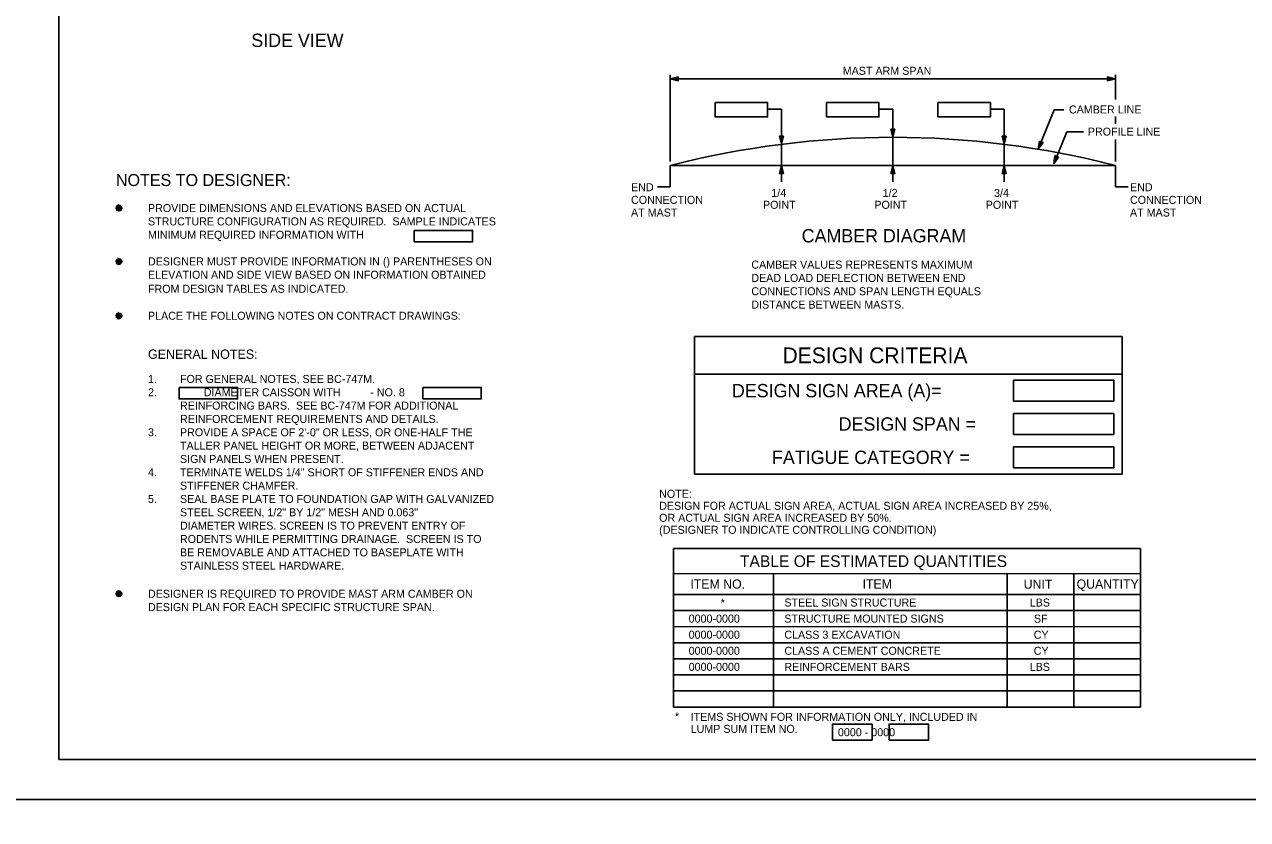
# Model space of a CAD drawing. Extents: x 640117 to 642655, y 297247 to 298435.
# Drawn here: x 640985.6 to 641443.9, y 297834 to 298132 of the extents above; entities that cross this region are included whole.
import ezdxf

# ---------------------------------------------------------------- set-up
doc = ezdxf.new("R2010")
doc.units = 0
for name, color, linetype in [('10', 7, 'Continuous'), ('17', 7, 'Continuous'), ('2', 7, 'Continuous'), ('52', 7, 'Continuous'), ('53', 7, 'Continuous'), ('55', 7, 'Continuous'), ('PLT-BNDY', 7, 'Continuous')]:
    doc.layers.add(name, color=color, linetype=linetype)

msp = doc.modelspace()

# ---------------------------------------------------------------- linework, layer by layer
at = {"layer": '10'}
for points in [[(641244.43, 298102.74), (641244.43, 298097.37), (641264.07, 298097.37), (641264.07, 298102.74)], [(641286.17, 298102.74), (641286.17, 298097.37), (641305.82, 298097.37), (641305.82, 298102.74)], [(641327.92, 298102.74), (641327.92, 298097.37), (641347.56, 298097.37), (641347.56, 298102.74)], [(641356.29, 297990.83), (641393.79, 297990.83), (641393.79, 297998.64), (641356.29, 297998.65)], [(641356.29, 297978.33), (641393.79, 297978.33), (641393.79, 297986.14), (641356.29, 297986.15)], [(641356.29, 297965.83), (641393.79, 297965.83), (641393.79, 297973.64), (641356.29, 297973.65)], [(641288.41, 297863.76), (641303.23, 297863.76), (641303.23, 297869.73), (641288.41, 297869.73)], [(641309.61, 297863.76), (641324.42, 297863.76), (641324.42, 297869.73), (641309.61, 297869.73)]]:
    msp.add_lwpolyline(points, close=True, dxfattribs=at)
at = {"layer": '17'}
for p, q in [((641396.92, 298014.99), (641236.73, 298014.99)), ((641236.73, 298014.99), (641236.73, 297963.49)), ((641396.92, 298014.99), (641396.92, 297963.49)), ((641236.73, 298000.99), (641396.92, 298000.99)), ((641236.73, 297963.49), (641396.92, 297963.49)), ((641228.81, 297935.51), (641228.81, 297876.12)), ((641403.81, 297935.51), (641228.81, 297935.51)), ((641403.81, 297935.51), (641403.81, 297876.12)), ((641403.81, 297926.13), (641228.81, 297926.14)), ((641266.31, 297926.14), (641266.31, 297876.12)), ((641353.81, 297926.13), (641353.81, 297876.13)), ((641378.81, 297926.13), (641378.81, 297876.13)), ((641403.81, 297918.32), (641228.81, 297918.32)), ((641403.81, 297912.29), (641228.81, 297912.3)), ((641403.81, 297906.26), (641228.81, 297906.27)), ((641403.81, 297900.23), (641228.81, 297900.24)), ((641403.81, 297894.21), (641228.81, 297894.21)), ((641403.81, 297888.18), (641228.81, 297888.18)), ((641403.81, 297882.15), (641228.81, 297882.15)), ((641403.81, 297876.12), (641228.81, 297876.12))]:
    msp.add_line(p, q, dxfattribs=at)
at = {"layer": '2'}
for p, q in [((640998.46, 297856.46), (640998.46, 298420.46)), ((641784.46, 297856.46), (640998.46, 297856.46))]:
    msp.add_line(p, q, dxfattribs=at)
for points in [[(641131.65, 298054.82), (641153.54, 298054.82), (641153.54, 298050.51), (641131.65, 298050.51)], [(641043.55, 297995.95), (641065.44, 297995.95), (641065.44, 297991.64), (641043.55, 297991.64)], [(641134.9, 297995.95), (641156.79, 297995.95), (641156.79, 297991.64), (641134.9, 297991.64)]]:
    msp.add_lwpolyline(points, close=True, dxfattribs=at)
for centre, radius in [((641020.98, 298063.2), 1.04), ((641020.98, 298063.2), 0.781), ((641020.98, 298063.2), 0.521), ((641020.98, 298063.2), 0.26), ((641020.98, 298063.2), 0.00000208), ((641020.98, 298043.12), 1.04), ((641020.98, 298043.12), 0.781), ((641020.98, 298043.12), 0.521), ((641020.98, 298043.12), 0.26), ((641020.98, 298043.12), 0.00000208), ((641020.98, 298022.75), 1.04), ((641020.98, 298022.75), 0.781), ((641020.98, 298022.75), 0.521), ((641020.98, 298022.75), 0.26), ((641020.98, 298022.75), 0.00000208), ((641020.98, 297918.62), 1.04), ((641020.98, 297918.62), 0.781), ((641020.98, 297918.62), 0.521), ((641020.98, 297918.62), 0.26), ((641020.98, 297918.62), 0.00000208)]:
    msp.add_circle(centre, radius, dxfattribs=at)
at = {"layer": '52'}
for p, q in [((641227.54, 298080.63), (641227.54, 298113.15)), ((641230.54, 298112.4), (641227.54, 298111.65)), ((641227.54, 298111.65), (641394.51, 298111.65)), ((641227.54, 298111.65), (641230.54, 298110.91)), ((641230.37, 298112.18), (641228.28, 298111.65)), ((641228.28, 298111.65), (641230.37, 298111.13)), ((641230.19, 298111.95), (641229.01, 298111.65)), ((641229.01, 298111.65), (641230.19, 298111.36)), ((641230.12, 298111.75), (641229.74, 298111.65)), ((641229.74, 298111.65), (641230.1, 298111.56)), ((641230.19, 298111.36), (641230.19, 298111.95)), ((641230.37, 298111.13), (641230.37, 298112.18)), ((641230.54, 298110.91), (641230.54, 298112.4)), ((641394.51, 298111.65), (641391.51, 298112.4)), ((641391.51, 298112.4), (641391.51, 298110.91)), ((641391.51, 298110.91), (641394.51, 298111.65)), ((641393.77, 298111.65), (641391.68, 298112.18)), ((641391.68, 298112.18), (641391.68, 298111.13)), ((641391.68, 298111.13), (641393.77, 298111.65)), ((641393.04, 298111.65), (641391.86, 298111.95)), ((641391.86, 298111.95), (641391.86, 298111.36)), ((641391.86, 298111.36), (641393.04, 298111.65)), ((641391.93, 298111.56), (641392.31, 298111.65)), ((641392.31, 298111.65), (641391.95, 298111.74)), ((641394.51, 298103.96), (641394.51, 298113.15)), ((641264.07, 298100.3), (641269.28, 298100.3)), ((641305.82, 298100.3), (641311.02, 298100.3)), ((641347.56, 298100.3), (641352.77, 298100.3)), ((641394.51, 298094.75), (641394.51, 298097.55)), ((641310.28, 298092.72), (641311.02, 298089.72)), ((641311.77, 298092.72), (641310.28, 298092.72)), ((641310.5, 298092.54), (641311.02, 298090.45)), ((641311.55, 298092.54), (641310.5, 298092.54)), ((641310.73, 298092.36), (641311.02, 298091.18)), ((641311.32, 298092.36), (641310.73, 298092.36)), ((641310.93, 298092.29), (641311.02, 298091.91)), ((641311.02, 298089.72), (641311.77, 298092.72)), ((641311.02, 298090.45), (641311.55, 298092.54)), ((641311.02, 298091.18), (641311.32, 298092.36)), ((641311.02, 298091.91), (641311.11, 298092.27)), ((641382.52, 298091.78), (641376.19, 298091.78)), ((641268.53, 298090.1), (641269.28, 298087.1)), ((641270.03, 298090.1), (641268.53, 298090.1)), ((641268.76, 298089.92), (641269.28, 298087.83)), ((641269.81, 298089.92), (641268.76, 298089.92)), ((641268.99, 298089.75), (641269.28, 298088.57)), ((641269.58, 298089.75), (641268.99, 298089.75)), ((641269.19, 298089.68), (641269.28, 298089.3)), ((641269.28, 298087.1), (641270.03, 298090.1)), ((641269.28, 298087.83), (641269.81, 298089.92)), ((641269.28, 298088.57), (641269.58, 298089.75)), ((641269.28, 298089.3), (641269.37, 298089.66)), ((641352.02, 298090.1), (641352.77, 298087.1)), ((641353.51, 298090.1), (641352.02, 298090.1)), ((641352.24, 298089.92), (641352.77, 298087.83)), ((641353.29, 298089.92), (641352.24, 298089.92)), ((641352.47, 298089.75), (641352.77, 298088.57)), ((641353.06, 298089.75), (641352.47, 298089.75)), ((641352.67, 298089.68), (641352.77, 298089.3)), ((641352.77, 298087.1), (641353.51, 298090.1)), ((641352.77, 298087.83), (641353.29, 298089.92)), ((641352.77, 298088.57), (641353.06, 298089.75)), ((641352.77, 298089.3), (641352.86, 298089.66)), ((641365.96, 298088.31), (641365.52, 298085.25)), ((641365.52, 298085.25), (641367.35, 298087.74)), ((641366.1, 298088.06), (641365.8, 298085.93)), ((641365.8, 298085.93), (641367.07, 298087.66)), ((641367.35, 298087.74), (641365.96, 298088.31)), ((641366.25, 298087.81), (641366.07, 298086.61)), ((641366.07, 298086.61), (641366.79, 298087.59)), ((641367.07, 298087.66), (641366.1, 298088.06)), ((641366.79, 298087.59), (641366.25, 298087.81)), ((641366.41, 298087.67), (641366.35, 298087.28)), ((641366.35, 298087.28), (641366.57, 298087.58)), ((641394.51, 298080.63), (641394.51, 298088.9)), ((641371.76, 298082.88), (641371.32, 298079.82)), ((641371.32, 298079.82), (641373.15, 298082.32)), ((641371.9, 298082.63), (641371.6, 298080.5)), ((641371.6, 298080.5), (641372.87, 298082.24)), ((641373.15, 298082.32), (641371.76, 298082.88)), ((641372.04, 298082.38), (641371.87, 298081.18)), ((641372.87, 298082.24), (641371.9, 298082.63)), ((641372.59, 298082.16), (641372.04, 298082.38)), ((641372.21, 298082.24), (641372.15, 298081.86)), ((641227.54, 298079.13), (641227.54, 298071.19)), ((641269.28, 298079.13), (641268.53, 298076.13)), ((641269.28, 298078.4), (641268.76, 298076.31)), ((641269.28, 298077.67), (641268.99, 298076.49)), ((641270.03, 298076.13), (641269.28, 298079.13)), ((641269.81, 298076.31), (641269.28, 298078.4)), ((641269.58, 298076.49), (641269.28, 298077.67)), ((641311.02, 298079.13), (641310.28, 298076.13)), ((641311.02, 298078.4), (641310.5, 298076.31)), ((641311.02, 298077.67), (641310.73, 298076.49)), ((641311.77, 298076.13), (641311.02, 298079.13)), ((641311.55, 298076.31), (641311.02, 298078.4)), ((641311.32, 298076.49), (641311.02, 298077.67)), ((641352.77, 298079.13), (641352.02, 298076.13)), ((641352.77, 298078.4), (641352.24, 298076.31)), ((641352.77, 298077.67), (641352.47, 298076.49)), ((641353.51, 298076.13), (641352.77, 298079.13)), ((641353.29, 298076.31), (641352.77, 298078.4)), ((641353.06, 298076.49), (641352.77, 298077.67)), ((641371.87, 298081.18), (641372.59, 298082.16)), ((641372.15, 298081.86), (641372.37, 298082.15)), ((641394.51, 298079.13), (641394.51, 298071.19)), ((641268.53, 298076.13), (641270.03, 298076.13)), ((641268.76, 298076.31), (641269.81, 298076.31)), ((641268.99, 298076.49), (641269.58, 298076.49)), ((641269.28, 298076.93), (641269.19, 298076.58)), ((641269.38, 298076.56), (641269.28, 298076.93)), ((641310.28, 298076.13), (641311.77, 298076.13)), ((641310.5, 298076.31), (641311.55, 298076.31)), ((641310.73, 298076.49), (641311.32, 298076.49)), ((641311.02, 298076.93), (641310.93, 298076.58)), ((641311.12, 298076.56), (641311.02, 298076.93)), ((641352.02, 298076.13), (641353.51, 298076.13)), ((641352.24, 298076.31), (641353.29, 298076.31)), ((641352.47, 298076.49), (641353.06, 298076.49)), ((641352.77, 298076.93), (641352.68, 298076.58)), ((641352.86, 298076.56), (641352.77, 298076.93)), ((641222.79, 298071.19), (641227.54, 298071.19)), ((641394.51, 298071.19), (641399.26, 298071.19))]:
    msp.add_line(p, q, dxfattribs=at)
for points in [[(641269.28, 298072.98), (641269.28, 298100.3)], [(641311.02, 298072.98), (641311.02, 298100.3)], [(641352.77, 298072.98), (641352.77, 298100.3)], [(641365.52, 298085.25), (641371.53, 298100), (641375.06, 298100)], [(641371.32, 298079.82), (641376.19, 298091.78)]]:
    msp.add_lwpolyline(points, dxfattribs=at)
at = {"layer": '55'}
msp.add_line((641227.54, 298079.13), (641394.51, 298079.13), dxfattribs=at)
msp.add_arc((641311.02, 297755.16), 334.56, 75.5503, 104.4497, dxfattribs=at)
at = {"layer": 'PLT-BNDY'}
for points in [[(640958.46, 298435.46), (641799.46, 298435.46), (641799.46, 297841.46), (640958.46, 297841.46)], [(640958.46, 297841.46), (641799.46, 297841.46), (641799.46, 297247.46), (640958.46, 297247.46)]]:
    msp.add_lwpolyline(points, close=True, dxfattribs=at)

# ---------------------------------------------------------------- texts
at = {"layer": '10'}
msp.add_text('NOTES TO DESIGNER:', height=4.5, dxfattribs=at).set_placement((641019.86, 298071.46))
at = {"layer": '2'}
for s, height, p in [('DESIGN CRITERIA', 5.9062, (641269.66, 298005.04)), ('DESIGN SIGN AREA (A)=', 5, (641250.72, 297992.25)), ('DESIGN SPAN =', 5, (641290.72, 297979.75)), ('FATIGUE CATEGORY =', 5, (641265.72, 297967.25)), ('NOTE:', 3, (641223.44, 297954.58)), ('DESIGN FOR ACTUAL SIGN AREA, ACTUAL SIGN AREA INCREASED BY 25%,', 3, (641223.44, 297950.08)), ('OR ACTUAL SIGN AREA INCREASED BY 50%.', 3, (641223.44, 297945.58)), ('(DESIGNER TO INDICATE CONTROLLING CONDITION)', 3, (641223.44, 297941.08)), ('TABLE OF ESTIMATED QUANTITIES', 4.375, (641253.72, 297928.64)), ('ITEM NO.', 3.445, (641235.15, 297920.52)), ('ITEM', 3.445, (641299.67, 297920.52)), ('UNIT', 3.445, (641360.06, 297920.5)), ('QUANTITY', 3.445, (641379.89, 297920.52)), ('*', 3, (641246.48, 297913.82)), ('STEEL SIGN STRUCTURE', 3, (641270.36, 297913.82)), ('LBS', 3, (641362.33, 297913.81)), ('0000-0000', 3, (641234.5, 297907.79)), ('STRUCTURE MOUNTED SIGNS', 3, (641270.36, 297907.79)), ('SF', 3, (641363.89, 297907.78)), ('0000-0000', 3, (641234.5, 297901.76)), ('CLASS 3 EXCAVATION', 3, (641270.36, 297901.76)), ('CY', 3, (641363.81, 297901.76)), ('0000-0000', 3, (641234.5, 297895.73)), ('CLASS A CEMENT CONCRETE', 3, (641270.36, 297895.73)), ('CY', 3, (641363.81, 297895.73)), ('0000-0000', 3, (641234.5, 297889.7)), ('REINFORCEMENT BARS', 3, (641270.36, 297889.7)), ('LBS', 3, (641362.33, 297889.7)), ('*', 3, (641229.39, 297871.12)), ('ITEMS SHOWN FOR INFORMATION ONLY, INCLUDED IN', 3, (641235.25, 297870.96)), ('LUMP SUM ITEM NO. ', 3, (641235.25, 297866.46)), ('0000 - 0000', 3, (641290.44, 297865.2))]:
    msp.add_text(s, height=height, dxfattribs=at).set_placement(p)
at = {"layer": '52'}
msp.add_text('MAST ARM SPAN', height=3, dxfattribs=at).set_placement((641292.24, 298113.15))
at = {"layer": '53'}
for s, height, p in [('SIDE VIEW', 5, (641070.6, 298123.59)), ('CAMBER LINE', 3, (641377.01, 298098.66)), ('PROFILE LINE', 3, (641384.1, 298090.36)), ('END', 3, (641212.9, 298069.52)), ('END', 3, (641399.89, 298069.52)), ('*', 3, (641019.86, 298061.7)), ('PROVIDE DIMENSIONS AND ELEVATIONS BASED ON ACTUAL ', 3, (641031.86, 298061.7)), ('CONNECTION', 3, (641212.9, 298064.77)), ('CONNECTION ', 3, (641399.89, 298064.77)), ('STRUCTURE CONFIGURATION AS REQUIRED.  SAMPLE INDICATES ', 3, (641031.86, 298056.7)), ('AT MAST', 3, (641212.9, 298060.02)), ('AT MAST', 3, (641399.89, 298060.02)), ('MINIMUM REQUIRED INFORMATION WITH', 3, (641031.86, 298051.7)), ('CAMBER DIAGRAM', 5, (641276.85, 298050.32)), ('*', 3, (641019.86, 298041.7)), ('DESIGNER MUST PROVIDE INFORMATION IN () PARENTHESES ON ', 3, (641031.86, 298041.7)), ('CAMBER VALUES REPRESENTS MAXIMUM', 3, (641257.98, 298040.51)), ('ELEVATION AND SIDE VIEW BASED ON INFORMATION OBTAINED ', 3, (641031.86, 298036.7)), ('DEAD LOAD DEFLECTION BETWEEN END', 3, (641257.98, 298035.51)), ('FROM DESIGN TABLES AS INDICATED. ', 3, (641031.86, 298031.42)), ('CONNECTIONS AND SPAN LENGTH EQUALS', 3, (641257.98, 298030.51)), ('DISTANCE BETWEEN MASTS.', 3, (641257.98, 298025.51)), ('*', 3, (641019.86, 298021.33)), ('PLACE THE FOLLOWING NOTES ON CONTRACT DRAWINGS: ', 3, (641031.86, 298021.33)), ('GENERAL NOTES:', 3.5, (641031.86, 298006.67)), ('1.', 3, (641031.86, 297997.64)), ('FOR GENERAL NOTES, SEE BC-747M.', 3, (641043.86, 297997.64)), ('2.', 3, (641031.86, 297992.64)), ('        DIAMETER CAISSON WITH          - NO. 8 ', 3, (641043.86, 297992.64)), ('REINFORCING BARS.  SEE BC-747M FOR ADDITIONAL ', 3, (641043.86, 297987.64)), ('REINFORCEMENT REQUIREMENTS AND DETAILS.', 3, (641043.86, 297982.64)), ('3.', 3, (641031.86, 297977.64)), ('PROVIDE A SPACE OF 2\'-0" OR LESS, OR ONE-HALF THE ', 3, (641043.86, 297977.64)), ('TALLER PANEL HEIGHT OR MORE, BETWEEN ADJACENT ', 3, (641043.86, 297972.64)), ('SIGN PANELS WHEN PRESENT.', 3, (641043.86, 297967.64)), ('4.', 3, (641031.86, 297962.64)), ('TERMINATE WELDS 1/4" SHORT OF STIFFENER ENDS AND ', 3, (641043.86, 297962.64)), ('STIFFENER CHAMFER.', 3, (641043.86, 297957.64)), ('5.', 3, (641031.86, 297952.64)), ('SEAL BASE PLATE TO FOUNDATION GAP WITH GALVANIZED ', 3, (641043.86, 297952.64)), ('STEEL SCREEN, 1/2" BY 1/2" MESH AND 0.063" ', 3, (641043.86, 297947.64)), ('DIAMETER WIRES. SCREEN IS TO PREVENT ENTRY OF ', 3, (641043.86, 297942.64)), ('RODENTS WHILE PERMITTING DRAINAGE.  SCREEN IS TO ', 3, (641043.86, 297937.64)), ('BE REMOVABLE AND ATTACHED TO BASEPLATE WITH ', 3, (641043.86, 297932.64)), ('STAINLESS STEEL HARDWARE. ', 3, (641043.86, 297927.64)), ('DESIGNER IS REQUIRED TO PROVIDE MAST ARM CAMBER ON ', 3, (641031.86, 297917.1)), ('DESIGN PLAN FOR EACH SPECIFIC STRUCTURE SPAN.', 3, (641031.86, 297912.1))]:
    msp.add_text(s, height=height, dxfattribs=at).set_placement(p)
for s, p in [('1/4', (641265.47, 298067.37)), ('1/2', (641307.21, 298067.37)), ('3/4', (641348.95, 298067.37)), ('POINT', (641262.35, 298062.93)), ('POINT', (641304.09, 298062.93)), ('POINT', (641345.83, 298062.93))]:
    msp.add_text(s, height=3, rotation=360, dxfattribs=at).set_placement(p)

doc.saveas('drawing.dxf')
